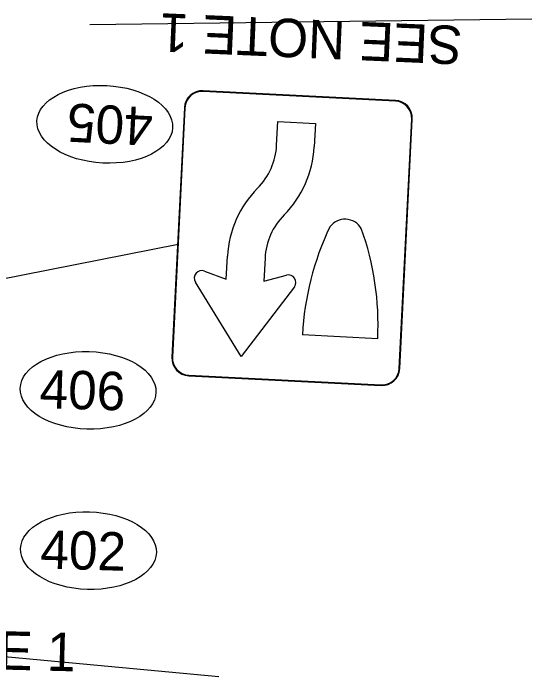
# Model space of a CAD drawing. Extents: x 2096670 to 2098561, y 684033 to 689893.
# Drawn here: x 2097859.5 to 2098021.5, y 686753.6 to 686960.8 of the extents above; entities that cross this region are included whole.
import ezdxf

# ---------------------------------------------------------------- set-up
doc = ezdxf.new("R2010")
doc.units = 0
for name, color, linetype in [('Prop DSN Text', 7, 'Continuous'), ('Prop Sign E Keep Right CELL', 7, 'Continuous'), ('Prop Sign E One Way_Right CELL', 7, 'Continuous'), ('Scratch_Level_3', 7, 'Continuous')]:
    doc.layers.add(name, color=color, linetype=linetype)

# ---------------------------------------------------------------- blocks, each defined once
blk = doc.blocks.new('R4_7A')
at = {"layer": 'Prop Sign E Keep Right CELL'}
blk.add_line((0.563, 6.375), (2.563, 6.375), dxfattribs=at)
blk.add_line((0.563, 6.375), (2.563, 6.375), dxfattribs=at)
blk.add_line((0.563, 6.375), (2.563, 6.375), dxfattribs=at)
for points in [[(2.841, 5.115), (4.156, 7.031), (5.471, 5.115)], [(2.841, 5.115), (4.156, 7.031), (5.471, 5.115)], [(2.841, 5.115), (4.156, 7.031), (5.471, 5.115)], [(3.656, 4.387), (3.656, 4.998), (3.067, 4.811)], [(3.656, 4.387), (3.656, 4.998), (3.067, 4.811)], [(3.656, 4.387), (3.656, 4.998), (3.067, 4.811)], [(5.246, 4.811), (4.656, 4.998), (4.656, 4.387)], [(5.246, 4.811), (4.656, 4.998), (4.656, 4.387)], [(5.246, 4.811), (4.656, 4.998), (4.656, 4.387)], [(3.5, 1.375), (3.5, 0.75), (2.5, 0.75), (2.5, 1.375)], [(3.5, 1.375), (3.5, 0.75), (2.5, 0.75), (2.5, 1.375)], [(3.5, 1.375), (3.5, 0.75), (2.5, 0.75), (2.5, 1.375)]]:
    blk.add_lwpolyline(points, dxfattribs=at)
for centre, radius, start, end in [((8.062, 6.373), 7.5, 179.9823, 202.7267), ((8.062, 6.373), 7.5, 179.9823, 202.7267), ((8.062, 6.373), 7.5, 179.9823, 202.7267), ((-4.938, 6.373), 7.5, 337.2733, 0.0177), ((-4.938, 6.373), 7.5, 337.2733, 0.0177), ((-4.938, 6.373), 7.5, 337.2733, 0.0177), ((3.006, 5.001), 0.2, 145.5508, 287.601), ((3.006, 5.001), 0.2, 145.5508, 287.601), ((3.006, 5.001), 0.2, 145.5508, 287.601), ((5.306, 5.001), 0.2, 252.399, 34.4492), ((5.306, 5.001), 0.2, 252.399, 34.4492), ((5.306, 5.001), 0.2, 252.399, 34.4492), ((1.906, 4.387), 1.75, 317.9924, 0), ((1.906, 4.387), 1.75, 317.9924, 0), ((1.906, 4.387), 1.75, 317.9924, 0), ((1.906, 4.387), 2.75, 317.9924, 0), ((1.906, 4.387), 2.75, 317.9924, 0), ((1.906, 4.387), 2.75, 317.9924, 0), ((1.562, 3.75), 0.5, 213.3458, 326.6542), ((1.562, 3.75), 0.5, 213.3458, 326.6542), ((1.562, 3.75), 0.5, 213.3458, 326.6542), ((5.25, 1.375), 2.75, 137.9924, 180), ((5.25, 1.375), 2.75, 137.9924, 180), ((5.25, 1.375), 2.75, 137.9924, 180), ((5.25, 1.375), 1.75, 137.9924, 180), ((5.25, 1.375), 1.75, 137.9924, 180), ((5.25, 1.375), 1.75, 137.9924, 180)]:
    blk.add_arc(centre, radius, start, end, dxfattribs=at)

msp = doc.modelspace()

# ---------------------------------------------------------------- linework, layer by layer
at = {"layer": 'Prop Sign E Keep Right CELL'}
for p, q in [((2097978.92, 686933.43), (2097918.83, 686936.44)), ((2097978.93, 686933.62), (2097918.84, 686936.62)), ((2097978.93, 686933.62), (2097978.92, 686933.43)), ((2097978.93, 686933.62), (2097978.92, 686933.43)), ((2097912.99, 686931.34), (2097909.09, 686853.43)), ((2097913.18, 686931.33), (2097909.28, 686853.42)), ((2097980.14, 686849.88), (2097984.04, 686927.78)), ((2097980.32, 686849.87), (2097984.22, 686927.77)), ((2097914.38, 686847.59), (2097974.48, 686844.58)), ((2097914.39, 686847.78), (2097974.49, 686844.77))]:
    msp.add_line(p, q, dxfattribs=at)
for centre, radius, start, end in [((2097918.56, 686931.06), 5.57, 87.135, 177.135), ((2097918.56, 686931.06), 5.39, 87.135, 177.135), ((2097978.65, 686928.05), 5.39, 357.135, 87.135), ((2097978.65, 686928.05), 5.57, 357.135, 87.135), ((2097914.66, 686853.15), 5.57, 177.135, 267.135), ((2097914.66, 686853.15), 5.39, 177.135, 267.135), ((2097974.75, 686850.15), 5.57, 267.135, 357.135), ((2097974.75, 686850.15), 5.39, 267.135, 357.135)]:
    msp.add_arc(centre, radius, start, end, dxfattribs=at)
at = {"layer": 'Prop Sign E One Way_Right CELL'}
msp.add_line((2097722.77, 686851.48), (2097911.04, 686888.71), dxfattribs=at)
for centre, major_axis in [((2097888.13, 686926.16), (21.19, -1.07)), ((2097882.92, 686843.07), (21.21, -0.62)), ((2097883.04, 686793), (21.21, -0.62))]:
    msp.add_ellipse(centre, major_axis=major_axis, ratio=0.571429, dxfattribs=at)
at = {"layer": 'Scratch_Level_3'}
for p, q in [((2098021.53, 686959.02), (2097883.45, 686957.26)), ((2097923.78, 686753.61), (2097770.28, 686767.84))]:
    msp.add_line(p, q, dxfattribs=at)

# ---------------------------------------------------------------- block references
at = {"layer": 'Prop Sign E Keep Right CELL', "xscale": 11.767345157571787, "yscale": 11.767345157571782, "rotation": 177.13495873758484}
msp.add_blockref('R4_7A', (2097983.76, 686933.79), dxfattribs=at)

# ---------------------------------------------------------------- texts
at = {"layer": 'Prop DSN Text'}
for rotation, p in [(177.5195, (2098000.04, 686956.79)), (358.5578, (2097784.36, 686757.65))]:
    msp.add_text('SEE NOTE 1', height=12, rotation=rotation, dxfattribs=at).set_placement(p)
at = {"layer": 'Prop Sign E One Way_Right CELL'}
for s, rotation, p in [('405', 177.1009, (2097903.39, 686931.38)), ('406', 358.3384, (2097867.64, 686837.53)), ('402', 358.3384, (2097867.88, 686787.45))]:
    msp.add_text(s, height=11.98, rotation=rotation, dxfattribs=at).set_placement(p)

doc.saveas('drawing.dxf')
